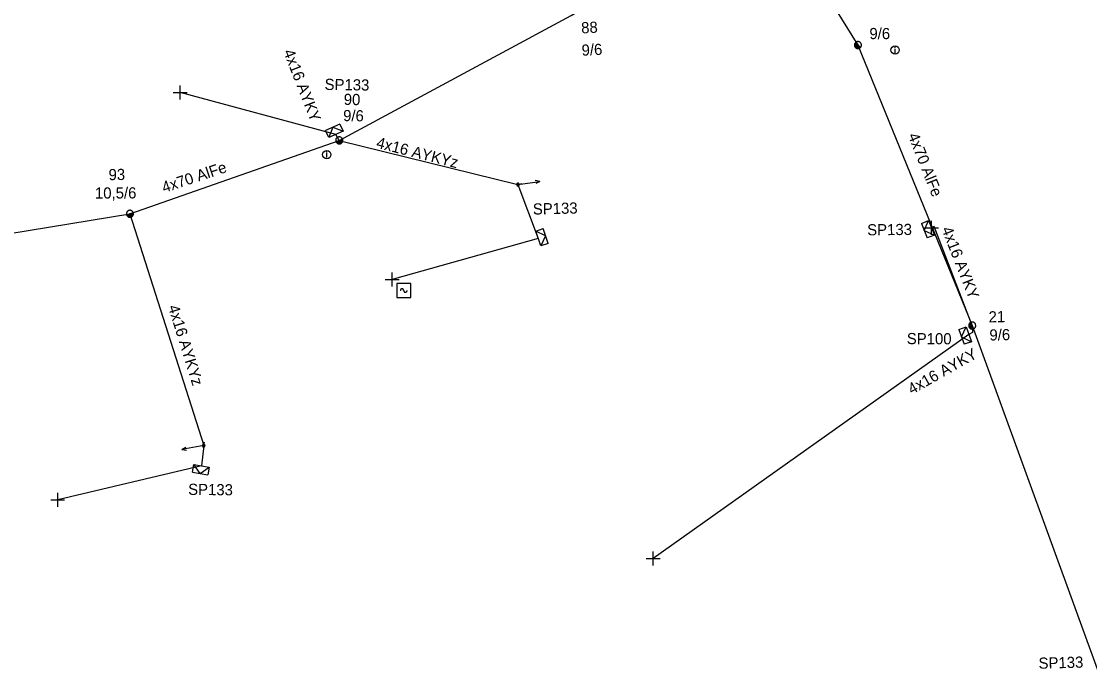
# Model space of a CAD drawing. Extents: x -748492 to -735633, y -1146251 to -1139940.
# Drawn here: x -740246.3 to -740150.5, y -1142203.1 to -1142144.9 of the extents above; entities that cross this region are included whole.
import ezdxf

# ---------------------------------------------------------------- set-up
doc = ezdxf.new("R2010")
doc.units = 0
for name, color, linetype in [('Vrstva 1', 7, 'Continuous'), ('Vrstva 10', 7, 'Continuous'), ('Vrstva 12', 7, 'Continuous'), ('Vrstva 13', 7, 'Continuous'), ('Vrstva 14', 7, 'Continuous'), ('Vrstva 2', 7, 'Continuous'), ('Vrstva 31', 7, 'Continuous'), ('Vrstva 33', 7, 'Continuous'), ('Vrstva 34', 7, 'Continuous'), ('Vrstva 36', 7, 'Continuous'), ('Vrstva 52', 7, 'Continuous'), ('Vrstva 54', 7, 'Continuous'), ('Vrstva 55', 7, 'Continuous'), ('Vrstva 59', 7, 'Continuous'), ('Vrstva 9', 7, 'Continuous')]:
    doc.layers.add(name, color=color, linetype=linetype)

# ---------------------------------------------------------------- blocks, each defined once
blk = doc.blocks.new('NN440')
at = {"layer": 'Vrstva 2'}
for points in [[(0.63, 0), (0.63, 0.06), (0.62, 0.13), (0.6, 0.19), (0.58, 0.25), (0.55, 0.31), (0.51, 0.37), (0.47, 0.42), (0.42, 0.46), (0.37, 0.51), (0.32, 0.54), (0.26, 0.57), (0.2, 0.59), (0.13, 0.61), (0.07, 0.62), (0, 0.63), (-0.06, 0.62), (-0.13, 0.61), (-0.19, 0.59), (-0.26, 0.57), (-0.31, 0.54), (-0.37, 0.51), (-0.42, 0.46), (-0.47, 0.42), (-0.51, 0.37), (-0.54, 0.31), (-0.57, 0.25), (-0.6, 0.19), (-0.62, 0.13), (-0.63, 0.06), (-0.63, 0), (-0.63, -0.07), (-0.62, -0.14), (-0.6, -0.2), (-0.57, -0.26), (-0.54, -0.32), (-0.51, -0.37), (-0.47, -0.43), (-0.42, -0.47), (-0.37, -0.51), (-0.31, -0.55), (-0.26, -0.58), (-0.19, -0.6), (-0.13, -0.62), (-0.06, -0.63), (0, -0.63), (0.07, -0.63), (0.13, -0.62), (0.2, -0.6), (0.26, -0.58), (0.32, -0.55), (0.37, -0.51), (0.42, -0.47), (0.47, -0.43), (0.51, -0.37), (0.55, -0.32), (0.58, -0.26), (0.6, -0.2), (0.62, -0.14), (0.63, -0.07), (0.63, 0)], [(-0.63, 0), (0.63, 0)], [(-0.6, -0.18), (0.57, -0.18)], [(-0.51, -0.32), (0.5, -0.32)], [(-0.37, -0.47), (0.35, -0.47)]]:
    blk.add_lwpolyline(points, dxfattribs=at)
blk = doc.blocks.new('NN560')
at = {"layer": 'Vrstva 2'}
for points in [[(1.999, -0.001), (1.59, 0.141)], [(0, -0.001), (1.999, -0.001)], [(1.999, -0.001), (1.59, -0.134)]]:
    blk.add_lwpolyline(points, dxfattribs=at)
blk = doc.blocks.new('NN770')
at = {"layer": 'Vrstva 10'}
for p, q in [((0.002, 0.187), (0.002, 0.263)), ((0.002, -0.276), (0.002, 0.111))]:
    blk.add_line(p, q, dxfattribs=at)
blk.add_circle((0, -0.008), 0.375, dxfattribs=at)
blk = doc.blocks.new('NN800')
at = {"layer": 'Vrstva 1'}
for points in [[(-0.442, 0.442), (0.442, -0.442)], [(-0.442, -0.442), (0.442, 0.442)]]:
    blk.add_lwpolyline(points, dxfattribs=at)
blk = doc.blocks.new('NN630')
at = {"layer": 'Vrstva 9'}
for points in [[(-0.003, -0.7), (-0.703, 0)], [(-0.703, -0.7), (-0.703, 0), (0.697, 0), (0.697, -0.7)], [(-0.703, -0.7), (0.697, -0.7)], [(-0.003, -0.7), (0.697, 0)]]:
    blk.add_lwpolyline(points, dxfattribs=at)
blk = doc.blocks.new('NN740')
at = {"layer": 'Vrstva 1'}
for points in [[(0.624, 0.624), (-0.626, 0.624)], [(-0.626, 0.624), (-0.626, -0.626)], [(-0.001, -0.001), (-0.002, 0.015), (-0.004, 0.031), (-0.008, 0.046), (-0.014, 0.061), (-0.021, 0.075), (-0.03, 0.089), (-0.04, 0.101), (-0.051, 0.112), (-0.063, 0.123), (-0.077, 0.131), (-0.091, 0.139), (-0.106, 0.145), (-0.121, 0.149), (-0.137, 0.151), (-0.153, 0.152), (-0.169, 0.151), (-0.185, 0.149), (-0.2, 0.145), (-0.215, 0.139), (-0.229, 0.132), (-0.243, 0.123), (-0.255, 0.113), (-0.266, 0.102), (-0.276, 0.09), (-0.285, 0.076), (-0.293, 0.062), (-0.298, 0.047), (-0.303, 0.032), (-0.305, 0.016), (-0.306, 0), (-0.306, -0.001)], [(0.624, -0.626), (0.624, 0.624)], [(-0.626, -0.626), (0.624, -0.626)], [(-0.001, -0.001), (0, -0.017), (0.002, -0.032), (0.006, -0.048), (0.011, -0.062), (0.018, -0.077), (0.026, -0.09), (0.036, -0.102), (0.047, -0.114), (0.059, -0.124), (0.072, -0.133), (0.085, -0.14), (0.1, -0.146), (0.115, -0.15), (0.131, -0.153), (0.146, -0.154), (0.162, -0.154), (0.178, -0.151), (0.193, -0.148), (0.208, -0.142), (0.222, -0.135), (0.235, -0.127), (0.247, -0.118), (0.259, -0.107), (0.269, -0.095), (0.278, -0.082), (0.285, -0.068), (0.291, -0.053), (0.295, -0.038), (0.298, -0.023), (0.299, -0.007), (0.299, -0.006)]]:
    blk.add_lwpolyline(points, dxfattribs=at)
blk = doc.blocks.new('NN500')
at = {"layer": 'Vrstva 2'}
for points in [[(0, -0.24), (0.02, -0.23), (0.05, -0.23), (0.07, -0.22), (0.09, -0.22), (0.12, -0.2), (0.14, -0.19), (0.16, -0.18), (0.17, -0.16), (0.19, -0.14), (0.2, -0.12), (0.21, -0.1), (0.22, -0.07), (0.23, -0.05), (0.23, -0.02), (0.23, 0), (0.23, 0.02), (0.23, 0.05), (0.22, 0.07), (0.21, 0.1), (0.2, 0.12), (0.19, 0.14), (0.17, 0.16), (0.16, 0.17), (0.14, 0.19), (0.12, 0.2), (0.09, 0.21), (0.07, 0.22), (0.05, 0.23), (0.02, 0.23), (0, 0.23), (-0.03, 0.23), (-0.05, 0.23), (-0.07, 0.22), (-0.1, 0.21), (-0.12, 0.2), (-0.14, 0.19), (-0.16, 0.17), (-0.18, 0.16), (-0.19, 0.14), (-0.2, 0.12), (-0.22, 0.1), (-0.22, 0.07), (-0.23, 0.05), (-0.23, 0.02), (-0.24, 0), (-0.23, -0.02), (-0.23, -0.05), (-0.22, -0.07), (-0.22, -0.1), (-0.2, -0.12), (-0.19, -0.14), (-0.18, -0.16), (-0.16, -0.18), (-0.14, -0.19), (-0.12, -0.2), (-0.1, -0.22), (-0.07, -0.22), (-0.05, -0.23), (-0.03, -0.23), (0, -0.24)], [(0, -0.24), (0.02, -0.23), (0.05, -0.23), (0.07, -0.22), (0.09, -0.22), (0.12, -0.2), (0.14, -0.19), (0.16, -0.18), (0.17, -0.16), (0.19, -0.14), (0.2, -0.12), (0.21, -0.1), (0.22, -0.07), (0.23, -0.05), (0.23, -0.02), (0.23, 0), (0.23, 0.02), (0.23, 0.05), (0.22, 0.07), (0.21, 0.1), (0.2, 0.12), (0.19, 0.14), (0.17, 0.16), (0.16, 0.17), (0.14, 0.19), (0.12, 0.2), (0.09, 0.21), (0.07, 0.22), (0.05, 0.23), (0.02, 0.23), (0, 0.23), (-0.03, 0.23), (-0.05, 0.23), (-0.07, 0.22), (-0.1, 0.21), (-0.12, 0.2), (-0.14, 0.19), (-0.16, 0.17), (-0.18, 0.16), (-0.19, 0.14), (-0.2, 0.12), (-0.22, 0.1), (-0.22, 0.07), (-0.23, 0.05), (-0.23, 0.02), (-0.24, 0), (-0.23, -0.02), (-0.23, -0.05), (-0.22, -0.07), (-0.22, -0.1), (-0.2, -0.12), (-0.19, -0.14), (-0.18, -0.16), (-0.16, -0.18), (-0.14, -0.19), (-0.12, -0.2), (-0.1, -0.22), (-0.07, -0.22), (-0.05, -0.23), (-0.03, -0.23), (0, -0.24)], [(0, -0.21), (0.02, -0.2), (0.04, -0.2), (0.06, -0.2), (0.08, -0.19), (0.1, -0.18), (0.12, -0.17), (0.14, -0.15), (0.15, -0.14), (0.16, -0.12), (0.18, -0.1), (0.19, -0.08), (0.19, -0.06), (0.2, -0.04), (0.2, -0.02), (0.2, 0), (0.2, 0.02), (0.2, 0.04), (0.19, 0.06), (0.19, 0.08), (0.18, 0.1), (0.16, 0.12), (0.15, 0.14), (0.14, 0.15), (0.12, 0.17), (0.1, 0.18), (0.08, 0.19), (0.06, 0.19), (0.04, 0.2), (0.02, 0.2), (0, 0.2), (-0.02, 0.2), (-0.04, 0.2), (-0.06, 0.19), (-0.08, 0.19), (-0.1, 0.18), (-0.12, 0.17), (-0.14, 0.15), (-0.15, 0.14), (-0.17, 0.12), (-0.18, 0.1), (-0.19, 0.08), (-0.2, 0.06), (-0.2, 0.04), (-0.21, 0.02), (-0.21, 0), (-0.21, -0.02), (-0.2, -0.04), (-0.2, -0.06), (-0.19, -0.08), (-0.18, -0.1), (-0.17, -0.12), (-0.15, -0.14), (-0.14, -0.15), (-0.12, -0.17), (-0.1, -0.18), (-0.08, -0.19), (-0.06, -0.2), (-0.04, -0.2), (-0.02, -0.2), (0, -0.21)], [(0, -0.18), (0.02, -0.18), (0.04, -0.17), (0.05, -0.17), (0.07, -0.16), (0.09, -0.15), (0.1, -0.14), (0.12, -0.13), (0.13, -0.12), (0.14, -0.1), (0.15, -0.09), (0.16, -0.07), (0.17, -0.05), (0.17, -0.04), (0.17, -0.02), (0.17, 0), (0.17, 0.02), (0.17, 0.04), (0.17, 0.05), (0.16, 0.07), (0.15, 0.09), (0.14, 0.1), (0.13, 0.12), (0.12, 0.13), (0.1, 0.14), (0.09, 0.15), (0.07, 0.16), (0.05, 0.17), (0.04, 0.17), (0.02, 0.17), (0, 0.18), (-0.02, 0.17), (-0.04, 0.17), (-0.06, 0.17), (-0.07, 0.16), (-0.09, 0.15), (-0.1, 0.14), (-0.12, 0.13), (-0.13, 0.12), (-0.14, 0.1), (-0.15, 0.09), (-0.16, 0.07), (-0.17, 0.05), (-0.17, 0.04), (-0.18, 0.02), (-0.18, 0), (-0.18, -0.02), (-0.17, -0.04), (-0.17, -0.05), (-0.16, -0.07), (-0.15, -0.09), (-0.14, -0.1), (-0.13, -0.12), (-0.12, -0.13), (-0.1, -0.14), (-0.09, -0.15), (-0.07, -0.16), (-0.06, -0.17), (-0.04, -0.17), (-0.02, -0.18), (0, -0.18)], [(0, -0.15), (0.01, -0.15), (0.03, -0.14), (0.04, -0.14), (0.06, -0.13), (0.07, -0.13), (0.08, -0.12), (0.1, -0.11), (0.11, -0.1), (0.12, -0.09), (0.13, -0.07), (0.13, -0.06), (0.14, -0.05), (0.14, -0.03), (0.14, -0.02), (0.14, 0), (0.14, 0.01), (0.14, 0.03), (0.14, 0.04), (0.13, 0.06), (0.13, 0.07), (0.12, 0.09), (0.11, 0.1), (0.1, 0.11), (0.08, 0.12), (0.07, 0.13), (0.06, 0.13), (0.04, 0.14), (0.03, 0.14), (0.01, 0.14), (0, 0.15), (-0.02, 0.14), (-0.03, 0.14), (-0.05, 0.14), (-0.06, 0.13), (-0.07, 0.13), (-0.09, 0.12), (-0.1, 0.11), (-0.11, 0.1), (-0.12, 0.09), (-0.13, 0.07), (-0.13, 0.06), (-0.14, 0.04), (-0.14, 0.03), (-0.15, 0.01), (-0.15, 0), (-0.15, -0.02), (-0.14, -0.03), (-0.14, -0.05), (-0.13, -0.06), (-0.13, -0.07), (-0.12, -0.09), (-0.11, -0.1), (-0.1, -0.11), (-0.09, -0.12), (-0.07, -0.13), (-0.06, -0.13), (-0.05, -0.14), (-0.03, -0.14), (-0.02, -0.15), (0, -0.15)], [(0, -0.12), (0.01, -0.12), (0.02, -0.11), (0.03, -0.11), (0.05, -0.11), (0.06, -0.1), (0.07, -0.09), (0.08, -0.09), (0.09, -0.08), (0.09, -0.07), (0.1, -0.06), (0.11, -0.05), (0.11, -0.04), (0.11, -0.02), (0.11, -0.01), (0.12, 0), (0.11, 0.01), (0.11, 0.02), (0.11, 0.04), (0.11, 0.05), (0.1, 0.06), (0.09, 0.07), (0.09, 0.08), (0.08, 0.09), (0.07, 0.09), (0.06, 0.1), (0.05, 0.11), (0.03, 0.11), (0.02, 0.11), (0.01, 0.12), (0, 0.12), (-0.01, 0.12), (-0.03, 0.11), (-0.04, 0.11), (-0.05, 0.11), (-0.06, 0.1), (-0.07, 0.09), (-0.08, 0.09), (-0.09, 0.08), (-0.1, 0.07), (-0.1, 0.06), (-0.11, 0.05), (-0.11, 0.04), (-0.12, 0.02), (-0.12, 0.01), (-0.12, 0), (-0.12, -0.01), (-0.12, -0.02), (-0.11, -0.04), (-0.11, -0.05), (-0.1, -0.06), (-0.1, -0.07), (-0.09, -0.08), (-0.08, -0.09), (-0.07, -0.09), (-0.06, -0.1), (-0.05, -0.11), (-0.04, -0.11), (-0.03, -0.11), (-0.01, -0.12), (0, -0.12)], [(0, -0.09), (0.01, -0.09), (0.02, -0.09), (0.03, -0.08), (0.03, -0.08), (0.04, -0.08), (0.05, -0.07), (0.06, -0.07), (0.06, -0.06), (0.07, -0.05), (0.07, -0.04), (0.08, -0.04), (0.08, -0.03), (0.08, -0.02), (0.09, -0.01), (0.09, 0), (0.09, 0.01), (0.08, 0.02), (0.08, 0.03), (0.08, 0.03), (0.07, 0.04), (0.07, 0.05), (0.06, 0.06), (0.06, 0.06), (0.05, 0.07), (0.04, 0.07), (0.03, 0.08), (0.03, 0.08), (0.02, 0.08), (0.01, 0.09), (0, 0.09), (-0.01, 0.09), (-0.02, 0.08), (-0.03, 0.08), (-0.04, 0.08), (-0.04, 0.07), (-0.05, 0.07), (-0.06, 0.06), (-0.07, 0.06), (-0.07, 0.05), (-0.08, 0.04), (-0.08, 0.03), (-0.08, 0.03), (-0.09, 0.02), (-0.09, 0.01), (-0.09, 0), (-0.09, -0.01), (-0.09, -0.02), (-0.08, -0.03), (-0.08, -0.04), (-0.08, -0.04), (-0.07, -0.05), (-0.07, -0.06), (-0.06, -0.07), (-0.05, -0.07), (-0.04, -0.08), (-0.04, -0.08), (-0.03, -0.08), (-0.02, -0.09), (-0.01, -0.09), (0, -0.09)], [(0, -0.06), (0, -0.06), (0.01, -0.06), (0.02, -0.05), (0.02, -0.05), (0.03, -0.05), (0.03, -0.05), (0.04, -0.04), (0.04, -0.04), (0.05, -0.03), (0.05, -0.03), (0.05, -0.02), (0.05, -0.02), (0.05, -0.01), (0.06, -0.01), (0.06, 0), (0.06, 0.01), (0.05, 0.01), (0.05, 0.02), (0.05, 0.02), (0.05, 0.03), (0.05, 0.03), (0.04, 0.04), (0.04, 0.04), (0.03, 0.05), (0.03, 0.05), (0.02, 0.05), (0.02, 0.05), (0.01, 0.06), (0, 0.06), (0, 0.06), (-0.01, 0.06), (-0.01, 0.06), (-0.02, 0.05), (-0.02, 0.05), (-0.03, 0.05), (-0.03, 0.05), (-0.04, 0.04), (-0.04, 0.04), (-0.05, 0.03), (-0.05, 0.03), (-0.05, 0.02), (-0.06, 0.02), (-0.06, 0.01), (-0.06, 0.01), (-0.06, 0), (-0.06, -0.01), (-0.06, -0.01), (-0.06, -0.02), (-0.05, -0.02), (-0.05, -0.03), (-0.05, -0.03), (-0.04, -0.04), (-0.04, -0.04), (-0.03, -0.05), (-0.03, -0.05), (-0.02, -0.05), (-0.02, -0.05), (-0.01, -0.06), (-0.01, -0.06), (0, -0.06)], [(0, -0.03), (0, -0.03), (0, -0.03), (0.01, -0.03), (0.01, -0.03), (0.01, -0.02), (0.02, -0.02), (0.02, -0.02), (0.02, -0.02), (0.02, -0.02), (0.02, -0.01), (0.02, -0.01), (0.03, -0.01), (0.03, -0.01), (0.03, 0), (0.03, 0), (0.03, 0), (0.03, 0.01), (0.03, 0.01), (0.02, 0.01), (0.02, 0.01), (0.02, 0.02), (0.02, 0.02), (0.02, 0.02), (0.02, 0.02), (0.01, 0.02), (0.01, 0.02), (0.01, 0.03), (0, 0.03), (0, 0.03), (0, 0.03), (0, 0.03), (-0.01, 0.03), (-0.01, 0.03), (-0.01, 0.02), (-0.02, 0.02), (-0.02, 0.02), (-0.02, 0.02), (-0.02, 0.02), (-0.02, 0.02), (-0.03, 0.01), (-0.03, 0.01), (-0.03, 0.01), (-0.03, 0.01), (-0.03, 0), (-0.03, 0), (-0.03, 0), (-0.03, -0.01), (-0.03, -0.01), (-0.03, -0.01), (-0.03, -0.01), (-0.02, -0.02), (-0.02, -0.02), (-0.02, -0.02), (-0.02, -0.02), (-0.02, -0.02), (-0.01, -0.03), (-0.01, -0.03), (-0.01, -0.03), (0, -0.03), (0, -0.03)], [(0.23, 0), (0.7, 0)]]:
    blk.add_lwpolyline(points, dxfattribs=at)

msp = doc.modelspace()

# ---------------------------------------------------------------- linework, layer by layer
at = {"layer": 'Vrstva 1'}
for points in [[(-740282.142, -1142160.14), (-740258.33, -1142165.66), (-740236.58, -1142162.11), (-740217.8, -1142155.53), (-740196.98, -1142144.33), (-740179.499, -1142133.73)], [(-740178.84, -1142134.792), (-740171.26, -1142146.99), (-740161.01, -1142172.13), (-740149.45, -1142203.88)]]:
    msp.add_lwpolyline(points, dxfattribs=at)
at = {"layer": 'Vrstva 52'}
for points in [[(-740217.8, -1142155.53), (-740218.1, -1142154.999)], [(-740161.009, -1142172.13), (-740164.43, -1142163.25), (-740164.66, -1142163.37)], [(-740161.009, -1142172.13), (-740160.99, -1142172.74), (-740161.31, -1142172.92)]]:
    msp.add_lwpolyline(points, dxfattribs=at)
at = {"layer": 'Vrstva 54'}
for points in [[(-740217.8, -1142155.53), (-740201.77, -1142159.49), (-740199.949, -1142164.32)], [(-740236.58, -1142162.11), (-740229.96, -1142182.89), (-740230.15, -1142184.708)]]:
    msp.add_lwpolyline(points, dxfattribs=at)
at = {"layer": 'Vrstva 59'}
for points in [[(-740218.1, -1142154.999), (-740232.06, -1142151.25)], [(-740199.949, -1142164.32), (-740213.06, -1142168)], [(-740161.31, -1142172.92), (-740189.63, -1142193)], [(-740230.149, -1142184.709), (-740243.06, -1142187.75)]]:
    msp.add_lwpolyline(points, dxfattribs=at)

# ---------------------------------------------------------------- block references
at = {"layer": 'Vrstva 13'}
for name, p, xscale, yscale, rotation in [('NN440', (-740171.26, -1142146.99), 0.49999999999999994, 0.5, -54.43137211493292), ('NN440', (-740217.801, -1142155.53), 0.5, 0.5, 18.44037219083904), ('NN500', (-740201.77, -1142159.49), 0.5, 0.5000000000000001, 15.596298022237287), ('NN440', (-740236.579, -1142162.11), 0.5000000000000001, 0.4999999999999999, 19.412523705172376), ('NN440', (-740161.01, -1142172.13), 0.5, 0.5, -68.81769996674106), ('NN500', (-740229.959, -1142182.889), 0.49999999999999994, 0.5000000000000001, 79.9481779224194)]:
    msp.add_blockref(name, p, dxfattribs=dict(at, xscale=xscale, yscale=yscale, rotation=rotation))
for p, rotation in [((-740201.77, -1142159.491), 8.04426489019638), ((-740229.959, -1142182.891), -170.2199389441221)]:
    msp.add_blockref('NN560', p, dxfattribs=dict(at, rotation=rotation))
at = {"layer": 'Vrstva 31'}
for p, rotation in [((-740218.099, -1142154.998), -155.8349117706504), ((-740164.661, -1142163.369), -68.39534446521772), ((-740199.949, -1142164.32), 108.44037223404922), ((-740161.311, -1142172.919), -70.34186652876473), ((-740230.149, -1142184.708), -10.703302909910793)]:
    msp.add_blockref('NN630', p, dxfattribs=dict(at, rotation=rotation))
at = {"layer": 'Vrstva 34', "rotation": 45}
for p in [(-740232.06, -1142151.25), (-740164.66, -1142163.37), (-740213.06, -1142168), (-740243.06, -1142187.75), (-740189.63, -1142193)]:
    msp.add_blockref('NN800', p, dxfattribs=at)
at = {"layer": 'Vrstva 34'}
msp.add_blockref('NN740', (-740212.013, -1142168.991), dxfattribs=at)
at = {"layer": 'Vrstva 36'}
for p in [(-740167.926, -1142147.425), (-740218.919, -1142156.804)]:
    msp.add_blockref('NN770', p, dxfattribs=at)

# ---------------------------------------------------------------- texts
at = {"layer": 'Vrstva 12'}
for s, rotation, p in [('9/6', 359.854, (-740170.236, -1142146.455)), ('9/6', 2.895, (-740196.031, -1142147.952)), ('9/6', 359, (-740217.461, -1142153.802)), ('10,5/6', 0.253, (-740239.714, -1142160.752)), ('9/6', 1.199, (-740159.457, -1142173.476))]:
    msp.add_text(s, height=1, rotation=rotation, dxfattribs=at).set_placement(p)
at = {"layer": 'Vrstva 14'}
for s, rotation, p in [('88', 2.895, (-740196.071, -1142145.947)), ('90', 359, (-740217.402, -1142152.351)), ('93', 0.88, (-740238.488, -1142159.103)), ('21', 1.199, (-740159.532, -1142171.855))]:
    msp.add_text(s, height=1, rotation=rotation, dxfattribs=at).set_placement(p)
at = {"layer": 'Vrstva 2'}
for rotation, p in [(291.605, (-740166.793, -1142155.088)), (18.44, (-740233.518, -1142160.255))]:
    msp.add_text('4x70 AlFe', height=1, rotation=rotation, dxfattribs=at).set_placement(p)
at = {"layer": 'Vrstva 33'}
for s, rotation, p in [('SP133', 359.042, (-740219.12, -1142151.006)), ('SP133', 1.486, (-740200.417, -1142162.188)), ('SP133', 0.555, (-740170.429, -1142164.048)), ('SP100', 359.667, (-740166.882, -1142173.794)), ('SP133', 359.347, (-740231.359, -1142187.308)), ('SP133', 1.557, (-740155.045, -1142202.898))]:
    msp.add_text(s, height=1, rotation=rotation, dxfattribs=at).set_placement(p)
at = {"layer": 'Vrstva 54'}
for rotation, p in [(291.378, (-740222.826, -1142147.587)), (291.42, (-740163.778, -1142163.484)), (29.546, (-740166.429, -1142178.344))]:
    msp.add_text('4x16 AYKY', height=1, rotation=rotation, dxfattribs=at).set_placement(p)
at = {"layer": 'Vrstva 55'}
for rotation, p in [(345.67, (-740214.539, -1142156.177)), (287.274, (-740233.168, -1142170.446))]:
    msp.add_text('4x16 AYKYz', height=1, rotation=rotation, dxfattribs=at).set_placement(p)

doc.saveas('drawing.dxf')
